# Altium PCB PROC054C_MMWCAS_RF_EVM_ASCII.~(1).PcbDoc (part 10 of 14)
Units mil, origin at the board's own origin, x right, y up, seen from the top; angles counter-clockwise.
Board outline 6299.21 x 5370.07 mil, 8 copper layers (L1 TOP, L2 GND, L3 SIGNAL 1, L4 GND, L5 SIGNAL 2, L6 SIGNAL 3, L7 GND, L8 BOTTOM), stack 53.5 mil thick; 775 components, 552 nets, 2648 pads, 7845 vias.
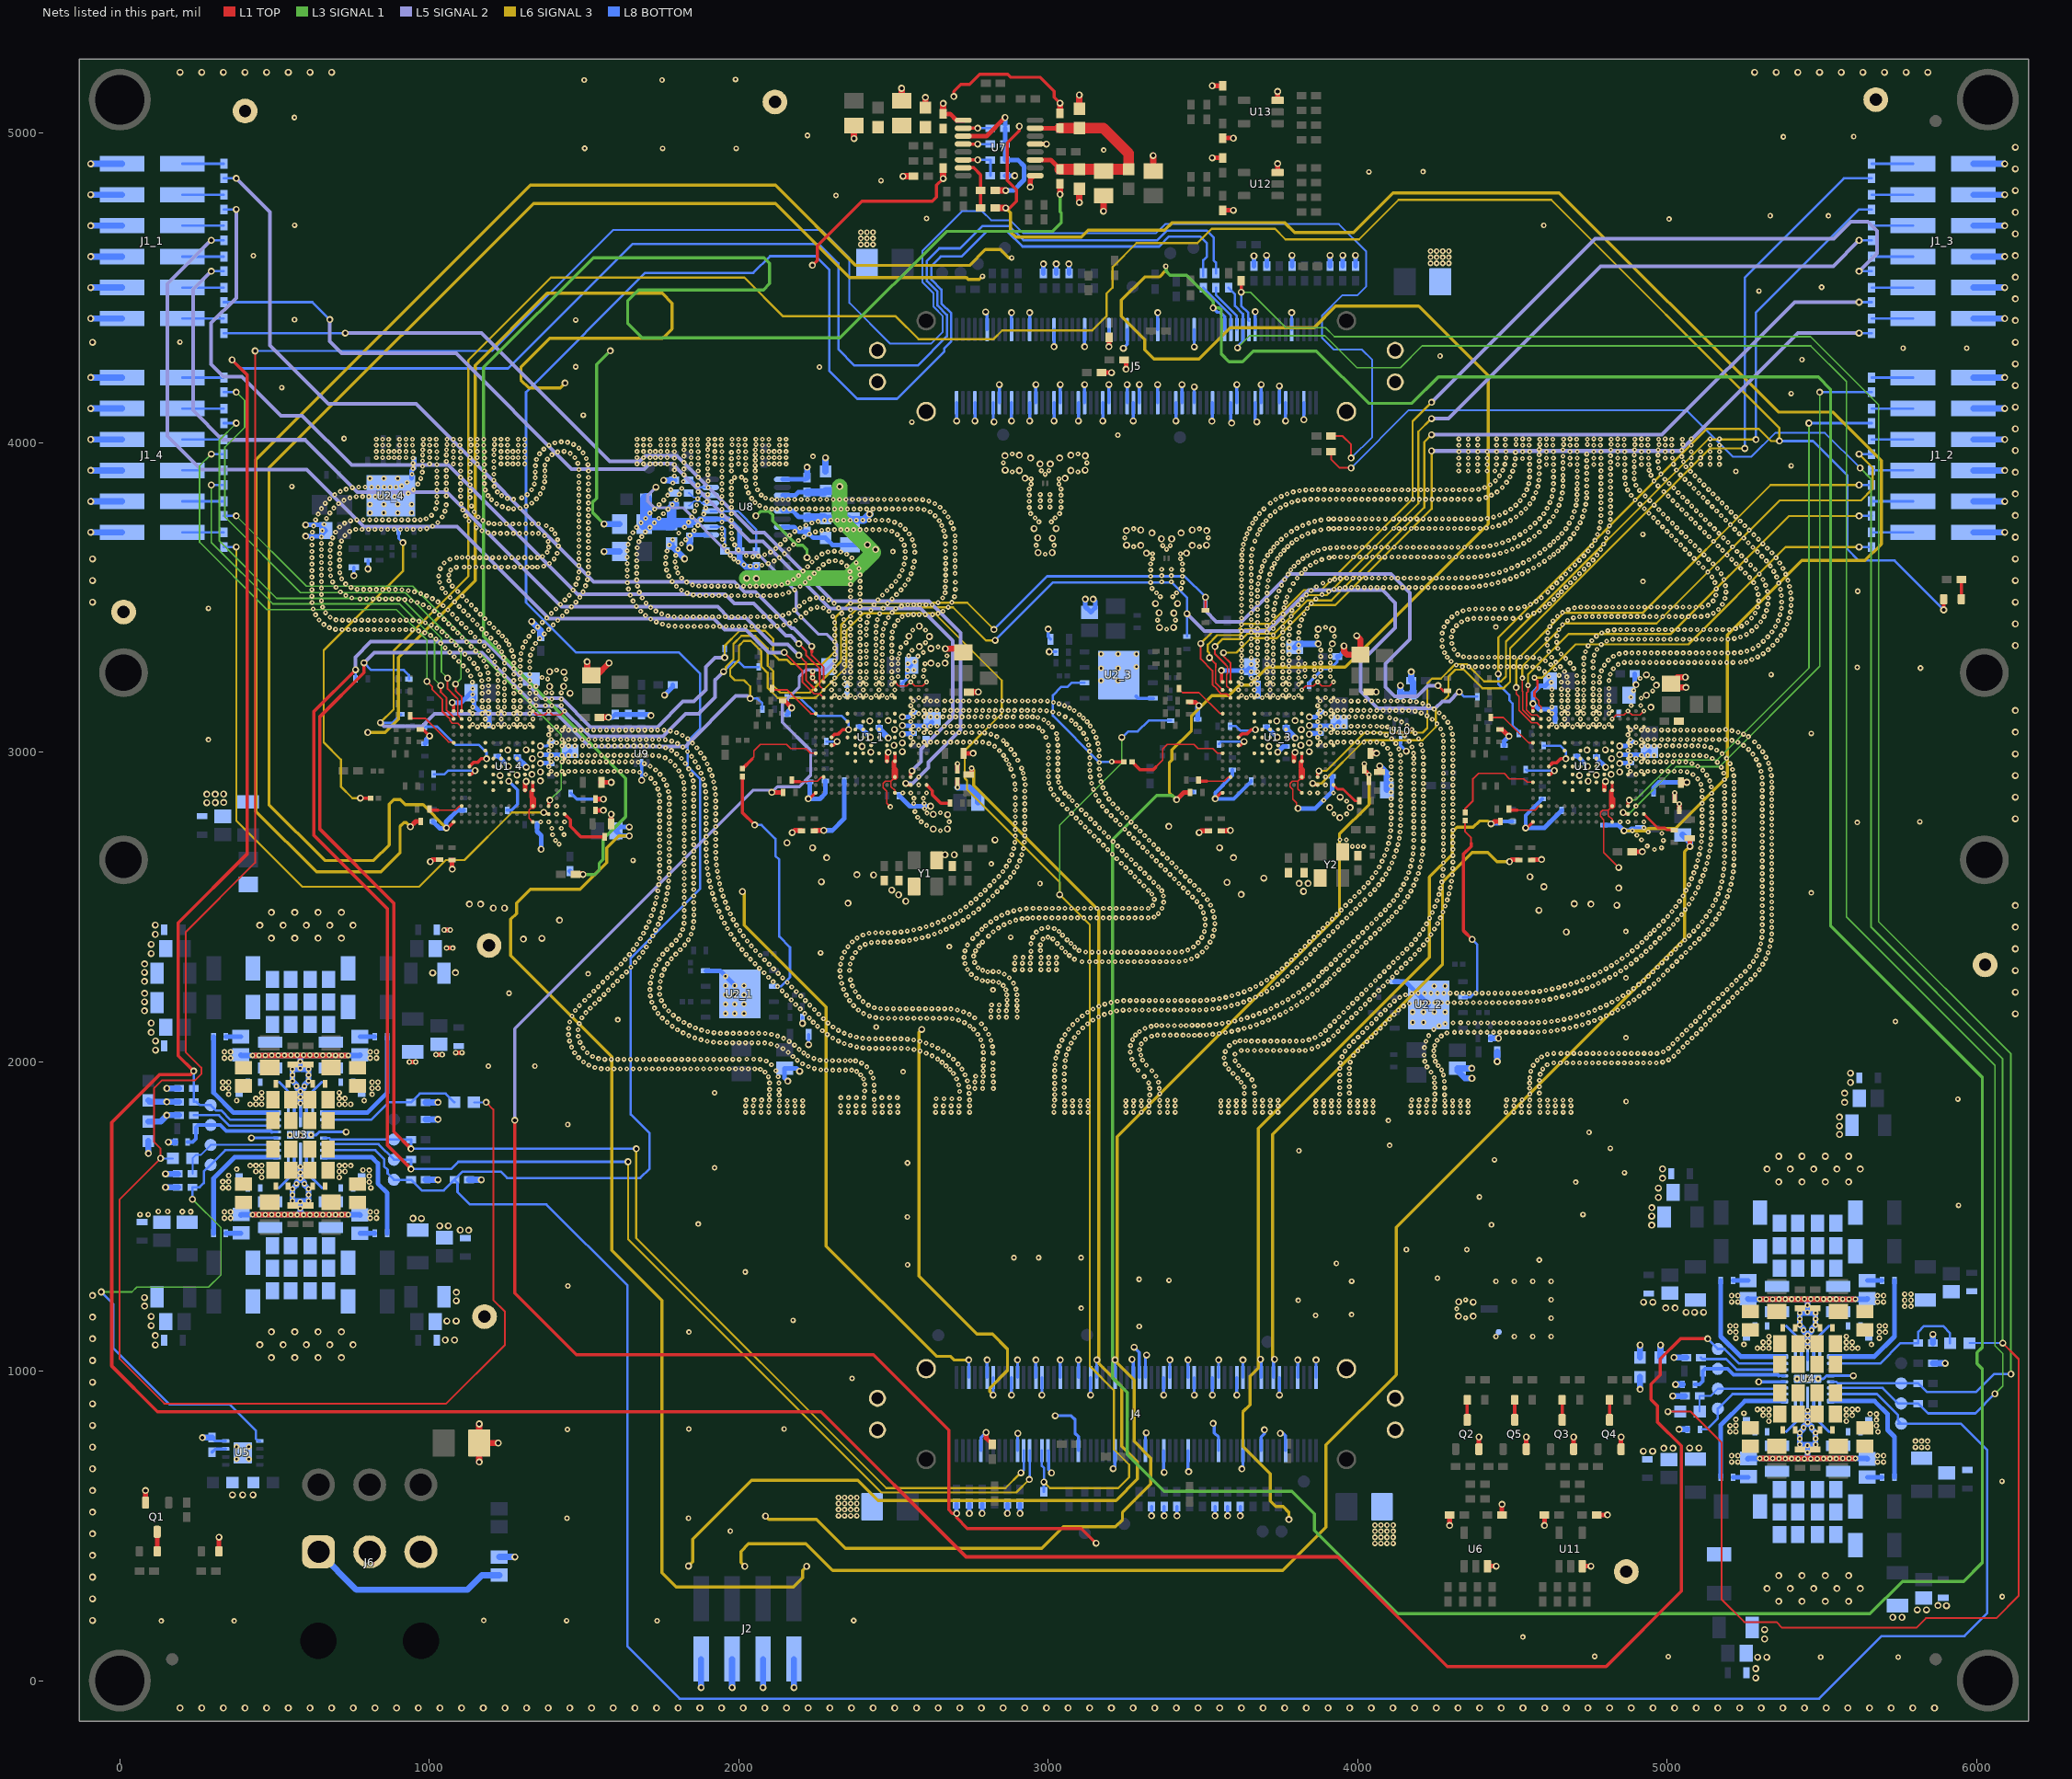
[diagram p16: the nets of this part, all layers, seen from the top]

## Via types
v1: diameter 13.77/15.74 (per signal layer), hole 5.9, L1 TOP to L2 GND, tented both sides, 5522 vias
v2: diameter 22.4, hole 12.2, L1 TOP to L8 BOTTOM, tented both sides, 1522 vias
v3: diameter 18, hole 8, L1 TOP to L8 BOTTOM, tented both sides, 727 vias
v4: diameter 18, hole 7.87, L1 TOP to L8 BOTTOM, tented top, 50 vias
v5: diameter 24, hole 12, L1 TOP to L8 BOTTOM, tented both sides, 13 vias
v6: diameter 19.68, hole 7.87, L1 TOP to L8 BOTTOM, tented top, 10 vias
v7: diameter 13.77/15.74 (per signal layer), hole 5.9, L1 TOP to L2 GND, tented top, 1 vias

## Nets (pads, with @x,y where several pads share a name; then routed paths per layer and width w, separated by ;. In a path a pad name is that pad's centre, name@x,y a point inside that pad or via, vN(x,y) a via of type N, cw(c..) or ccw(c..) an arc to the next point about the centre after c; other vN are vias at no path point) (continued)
GND: (continued)
  other v3: 5496.46,76.13 5746.88,75.69 5004.11,77.33 4766.22,78.16 4533.71,140.81 133.61,192.77 369.65,192.66 1735.9,193.46 1176.04,194.2 1443.98,193.71 2371.49,194.12 6083.21,271.3 4055.69,443.27 4075.37,443.27 4095.06,443.27 4114.74,443.27 4055.69,462.95 4075.37,462.95 4095.06,462.95 4114.74,462.95 1972.91,483.05 4055.69,482.64 4075.37,482.64 4095.06,482.64 4114.74,482.64 4055.69,502.32 4075.37,502.32 4095.06,502.32 4114.74,502.32 1444.93,524.87 1837.72,524.87 2322.39,532.65 2342.07,532.65 2361.76,532.65 2381.44,532.65 2322.39,552.33 2342.07,552.33 2361.76,552.33 2381.44,552.33 2322.39,572.02 2342.07,572.02 2361.76,572.02 2381.44,572.02 2322.39,591.7 2342.07,591.7 2361.76,591.7 2381.44,591.7 6082.36,644.09 5208.56,706.48 5228.64,706.48 5679.89,706.48 5699.97,706.48 5361.62,717.42 5382.2,717.42 5402.79,717.42 5423.38,717.03 5464.56,717.03 5485.14,717.03 5505.73,717.42 5526.32,717.42 5546.91,717.42 5208.56,726.56 5228.64,726.56 5679.89,726.56 5699.97,726.56 5453.83,737.78 5802.58,754.01 5822.27,754.01 5841.95,754.01 5480.24,762.36 5802.58,773.7 5822.27,773.7 5841.95,773.7 5480.24,781.54 5480.24,800.72 5203.41,804.46 5222.39,804.46 5681.81,804.28 1446.14,811.62 1838.91,813.25 2146.93,813.25 5467.25,817.49 5676.81,823.3 5203.39,824 5222.41,824.12 5676.81,842.33 5222.43,843.79 5676.81,861.35 5656.4,861.51 5248.32,864.12 2366.02,976.27 5248.32,1086.09 5660.21,1086.09 5222.43,1106.42 5686.1,1106.42 1839.11,1126.23 5203.39,1126.21 5222.41,1126.09 5686.12,1126.09 5705.13,1126.21 5467.25,1132.73 3294.2,1144.09 5203.41,1145.76 5222.39,1145.76 5686.14,1145.76 5705.12,1145.76 5480.24,1149.49 2175.59,1164.19 5480.24,1168.67 3863.89,1180.15 3980.44,1182.69 5480.24,1187.85 3106.88,1203.28 5768.24,1209.3 5787.93,1209.3 5453.83,1212.43 5208.56,1223.65 5228.64,1223.65 5679.89,1223.65 5699.97,1223.65 3808.19,1228.67 5768.24,1228.98 5787.93,1228.98 5361.62,1232.79 5382.2,1232.79 5402.79,1232.79 5423.38,1233.18 5464.56,1233.18 5485.14,1233.18 5505.73,1232.79 5526.32,1232.79 5546.91,1232.79 5208.56,1243.73 5228.64,1243.73 5679.89,1243.73 5699.97,1243.73 5768.24,1248.67 5787.93,1248.67 1447.63,1274.99 3980.74,1290.5 3390.59,1293.49 3294.08,1296.71 4258.14,1300.39 2020.86,1320.43 2545.46,1343.65 3931.42,1348.07 4587.06,1359.02 2889.33,1366.57 2969.15,1366.57 3106.43,1366.57 4353.05,1392.49 4157.58,1392.65 4432.48,1472.84 1869.17,1475.16 337.84,1494.34 357.91,1494.34 809.16,1494.34 829.24,1494.34 2544.96,1497.98 490.89,1505.28 511.48,1505.28 532.07,1505.28 552.66,1504.88 593.83,1504.88 614.42,1504.88 635.01,1505.28 655.6,1505.28 676.18,1505.28 65.22,1505.76 91.7,1505.76 4728.35,1506.03 337.84,1514.42 357.91,1514.42 809.16,1514.42 829.24,1514.42 201.83,1515.15 228.74,1515.15 124.35,1515.58 154.44,1515.58 583.11,1525.63 5942.02,1535.47 609.51,1550.22 4393.83,1562.75 609.51,1569.4 609.51,1588.57 332.68,1592.31 351.66,1592.31 811.08,1592.13 596.53,1605.34 806.08,1611.16 4704.66,1610.58 332.67,1611.86 351.68,1611.98 806.08,1630.18 351.7,1631.65 4862.1,1641.27 785.68,1649.37 806.08,1649.21 377.59,1651.98 1922,1656.9 2545.38,1672.67 4442.29,1682.92 3810.04,1712.1 4816.83,1720.08 4103.53,1729.5 4748.01,1771.34 1447.49,1796.86 4099.3,1809.49 4867.67,1870.96 377.59,1873.94 789.48,1873.94 5939.7,1878.97 351.7,1894.28 815.37,1894.28 1922,1899.1 332.67,1914.07 351.68,1913.94 815.39,1913.94 834.41,1914.07 596.53,1920.58 332.68,1933.61 351.66,1933.61 815.41,1933.61 834.39,1933.61 609.51,1937.35 609.51,1956.53 2531.24,1967.09 609.51,1975.71 1190.66,1985.23 1341.2,1985.23 583.11,2000.29 337.84,2011.51 357.91,2011.51 809.16,2011.51 829.24,2011.51 490.89,2020.65 511.48,2020.65 532.07,2020.65 552.66,2021.04 593.83,2021.04 614.42,2021.04 635.01,2020.65 655.6,2020.65 676.18,2020.65 337.84,2031.58 357.91,2031.58 809.16,2031.58 829.24,2031.58 4867.09,2077.1 2444.27,2111.49 5737.78,2129.64 1609.07,2135.05 1257.6,2220.99 2821.69,2231.51 4866.97,2270.39 1513.34,2283.69 2264.44,2351.62 2680.48,2371.52 2878.65,2401.99 4866.57,2420.19 5466.22,2545.1 2973.41,2575.67 2815.94,2638.69 1658.33,2650.13 5614.76,2772.56 5816.69,2774.88 286.24,3040.08 5466.22,3060.36 5336.44,3250.52 5819.01,3271.58 5614.76,3273.9 4446.74,3404.24 286.24,3464.59 5616.14,3519.73 4922.12,3551.17 2498.15,3647.68 4921.9,3703.62 555.74,3858.48 5222.3,3906.93 5401.14,3925.27 2239.73,3955.33 724.55,4013.2 3225.12,4024.15 2559.67,4066.48 1497.64,4088.75 5401.14,4158.65 523.21,4177.95 2260.51,4244.03 1473.37,4244.89 5435.94,4267.85 4266.52,4279.69 5762.98,4305.17 5968.42,4305.17 194.01,4324.78 1473.37,4396.3 564.38,4397.12 5297.15,4489.7 5499.56,4501.97 4235.61,4579.25 4255.29,4579.25 4274.98,4579.25 4294.66,4579.25 4235.61,4598.94 4255.29,4598.94 4274.98,4598.94 4294.66,4598.94 431.7,4603.8 4235.61,4618.62 4255.29,4618.62 4274.98,4618.62 4294.66,4618.62 2394.49,4640.14 2414.18,4640.14 2433.86,4640.14 2394.49,4659.82 2414.18,4659.82 2433.86,4659.82 2394.49,4679.51 2414.18,4679.51 2433.86,4679.51 564.74,4702.39 4601.73,4701.99 5006.36,4722.28 2607.24,4724.16 5333.41,4733.02 5521.43,4732.67 2314.4,4798.51 2459.82,4846.58 4036.41,4874.63 4211.46,4875.14 3179.55,4945.14 1502.16,4950.81 1753.92,4950.6 1991.93,4950.6 5375.87,4987.98 5603.32,4988.7 2221.82,4992.4 564.12,5050.42 1500.65,5171.71 1752.01,5171.71 1989.61,5173.43
  other v4: 4447.2,1111.73 4506.58,1111.73 4565.95,1111.73 4625.33,1111.73 4625.33,1171.11 4625.33,1230.48 4447.2,1289.85 4506.58,1289.85 4565.95,1289.85 4625.33,1289.85 4177.99,2126.74 4213.08,2126.74 1957.07,2155.57 1987.07,2155.57 2017.07,2155.57 4177.6,2160.03 4212.7,2160.03 4247.79,2160.03 4282.88,2160.03 1957.07,2185.57 1987.07,2185.57 2017.07,2185.57 1957.07,2215.57 1987.07,2215.57 2017.07,2215.57 4247.51,2243.88 4282.61,2243.88 1957.07,2245.57 1987.07,2245.57 2017.07,2245.57 1957.07,2275.57 3170.96,3230.95 3225.96,3230.95 3170.96,3270.95 3225.96,3270.95 3284.96,3275.95 3170.96,3316.95 3225.96,3316.95 3284.96,3316.95 808.11,3773.1 853.11,3773.1 898.11,3773.1 943.11,3773.1 808.11,3800.1 853.11,3800.1 898.11,3800.1 943.11,3800.1 808.11,3884.1 853.11,3884.1 898.11,3884.1
  other v6: 377.44,716.09 416.81,716.09 377.44,755.46 416.81,755.46 5420.01,975.11 549.29,1762.96
  other v7: 1435.24,2733.62
GND_SENSE: J6.1 R20.2 | length 654.6
  L8 BOTTOM w20: J6.1@642.01,416.24 764.9,293.36 1122.57,293.36 1169.82,340.61 R20.2@1226.16,340.61
GPADC1_1: R21_1.1 U1_1.P1 | length 2910.5
  L1 TOP w6: 2235.94,3323.61 2235.94,3313.08 2274.35,3274.67 U1_1.P1@2274.35,3226.63
  L1 TOP w10.5: 2235.94,3323.61 v2(2235.94,3341.84)
  L5 SIGNAL 2 w12: v2(376.34,4853.71) 484.59,4745.46 484.59,4313.48 673.16,4124.91 957.25,4124.91 1531.42,3550.74 1985.84,3550.74 2019.19,3517.39 2054.28,3517.39 2171.25,3400.42 2177.35,3400.42 v2(2235.94,3341.84)
  L8 BOTTOM w7.75: R21_1.1@335.85,4853.71 v2(376.34,4853.71)
GPADC1_2: R21_2.1 U1_2.P1 | length 1388.9
  L1 TOP w4: 4571.43,3180.57 4586.04,3165.96 4586.04,3152.41 4592.35,3146.1 U1_2.P1@4592.35,3132.63
  L1 TOP w8: 4571.43,3180.57 4571.43,3195.32 4580.76,3204.64 4580.76,3231.14 v3(4571.43,3240.47)
  L6 SIGNAL 3 w6.9: v3(4571.43,3240.47) 4596.67,3240.47 4704.44,3348.24 5069.13,3348.24 5383.78,3662.89 v2(5620.66,3662.89)
  L8 BOTTOM w7.75: v2(5620.66,3662.89) R21_2.1@5661.15,3662.89
GPADC1_3: R21_3.1 U1_3.P1 | length 2735.9
  L1 TOP w6: v2(3566.57,3321.12) 3566.57,3310 3589.35,3287.22 U1_3.P1@3589.35,3226.63
  L5 SIGNAL 2 w12: v2(4239,3973) 5042.9,3973 5423.61,4353.71 v2(5620.66,4353.71)
  L6 SIGNAL 3 w6.9: v2(3566.57,3321.12) 3608.23,3321.12 3655.5,3368.4 3739.36,3368.4 3845.99,3475.03 3928.21,3475.03 4239,3785.82 v2(4239,3973)
  L8 BOTTOM w7.75: v2(5620.66,4353.71) R21_3.1@5661.15,4353.71
GPADC1_4: R21_4.1 U1_4.P1 | length 1637.4
  L1 TOP w6: v2(1085,3220) 1085,3199.39 1104.35,3180.04 U1_4.P1@1104.35,3132.63
  L3 SIGNAL 1 w5.1: v2(376.34,4162.89) 403.51,4135.72 403.51,4049.61 339.61,3985.71 339.61,3759.61 584.15,3515.07 922.18,3515.07 1102.11,3335.14 1102.11,3237.11 v2(1085,3220)
  L8 BOTTOM w7.75: R21_4.1@335.85,4162.89 v2(376.34,4162.89)
GPADC1_CONN_1: J1_1.1 R21_1.2 | length 133.6
  L8 BOTTOM w7.75: J1_1.1@202.2,4900.95 R21_1.2@335.85,4900.95
GPADC1_CONN_2: J1_2.1 R21_2.2 | length 133.6
  L8 BOTTOM w7.75: R21_2.2@5661.15,3710.13 J1_2.1@5794.8,3710.13
GPADC1_CONN_3: J1_3.1 R21_3.2 | length 133.6
  L8 BOTTOM w7.75: R21_3.2@5661.15,4400.95 J1_3.1@5794.8,4400.95
GPADC1_CONN_4: J1_4.1 R21_4.2 | length 133.6
  L8 BOTTOM w7.75: J1_4.1@202.2,4210.13 R21_4.2@335.85,4210.13
GPADC2_1: R22_1.1 U1_1.P2 | length 3029.7
  L1 TOP w4: 2261.49,3235.84 2261.49,3213.9 U1_1.P2@2274.35,3201.04
  L1 TOP w6: v2(2194.09,3349.92) 2217.73,3326.28 2217.73,3313.24 2261.49,3269.48 2261.49,3235.84
  L5 SIGNAL 2 w12: v2(376.34,4753.71) 376.34,4467.74 295.19,4386.59 295.19,4253.33 335.16,4213.35 394.52,4213.35 520.64,4087.23 588.93,4087.23 748.84,3927.31 1061.01,3927.31 1478.43,3509.89 1955.91,3509.89 1985.77,3480.03 2048.08,3480.03 2152.21,3375.91 2168.1,3375.91 v2(2194.09,3349.92)
  L8 BOTTOM w7.75: R22_1.1@335.85,4753.71 v2(376.34,4753.71)
GPADC2_2: R22_2.1 U1_2.P2 | length 1497.9
  L1 TOP w4: 4545.62,3148.38 4545.62,3136.09 4561.81,3119.9 4579.49,3119.9 U1_2.P2@4592.35,3107.04
  L1 TOP w6: 4545.62,3148.38 4545.62,3191.12 4550.87,3196.38 v3(4550.87,3216.09)
  L6 SIGNAL 3 w6.9: v3(4550.87,3216.09) 4550.87,3250.62 4682.25,3381.99 5012.95,3381.99 5393.85,3762.89 v2(5620.66,3762.89)
  L8 BOTTOM w7.75: v2(5620.66,3762.89) R22_2.1@5661.15,3762.89
GPADC2_3: R22_3.1 U1_3.P2 | length 2870
  L1 TOP w4: 3573.3,3282.68 3579.29,3276.69 3579.29,3253.3 3576.39,3250.39 3576.39,3214 U1_3.P2@3589.35,3201.04
  L1 TOP w6: v2(3539,3341) 3539,3316.99 3573.3,3282.68
  L5 SIGNAL 2 w12: v2(4239,4025.33) 4983.76,4025.33 5412.13,4453.71 v2(5620.66,4453.71)
  L6 SIGNAL 3 w6.9: v2(3539,3341) 3562.87,3364.87 3625.69,3364.87 3643.85,3383.03 3730.83,3383.03 3838.22,3490.42 3915.31,3490.42 4215.47,3790.59 4215.47,4001.81 v2(4239,4025.33)
  L8 BOTTOM w7.75: v2(5620.66,4453.71) R22_3.1@5661.15,4453.71
GPADC2_4: R22_4.1 U1_4.P2 | length 1579.6
  L1 TOP w4: 1086.33,3177.31 1091.49,3172.15 1091.49,3119.9 U1_4.P2@1104.35,3107.04
  L1 TOP w6: v2(1059,3239) 1059,3204.64 1086.33,3177.31
  L3 SIGNAL 1 w5.1: v2(376.34,4062.89) 321.76,4008.31 321.76,3681.81 507.14,3496.43 910.93,3496.43 1039.1,3368.26 1039.1,3258.9 v2(1059,3239)
  L8 BOTTOM w7.75: R22_4.1@335.85,4062.89 v2(376.34,4062.89)
GPADC2_CONN_1: J1_1.3 R22_1.2 | length 133.6
  L8 BOTTOM w7.75: J1_1.3@202.2,4800.95 R22_1.2@335.85,4800.95
GPADC2_CONN_2: J1_2.3 R22_2.2 | length 133.6
  L8 BOTTOM w7.75: R22_2.2@5661.15,3810.13 J1_2.3@5794.8,3810.13
GPADC2_CONN_3: J1_3.3 R22_3.2 | length 133.6
  L8 BOTTOM w7.75: R22_3.2@5661.15,4500.95 J1_3.3@5794.8,4500.95
GPADC2_CONN_4: J1_4.3 R22_4.2 | length 133.6
  L8 BOTTOM w7.75: J1_4.3@202.2,4110.13 R22_4.2@335.85,4110.13
GPADC3_1: R23_1.1 U1_1.P3 | length 3224.7
  L1 TOP w4: 2232,3200 2244,3188 2261.8,3188 U1_1.P3@2274.35,3175.45
  L1 TOP w6: v2(2147,3322) 2205.54,3263.46 2205.54,3226.46 2232,3200
  L5 SIGNAL 2 w12: v2(295.35,4653.71) 294.32,4653.71 154.03,4513.42 154.03,4020.74 262.2,3912.57 604.09,3912.57 787.75,3728.91 1089.55,3728.91 1387.22,3431.24 1919.62,3431.24 1954.92,3395.94 2022.73,3395.94 2096.68,3322 v2(2147,3322)
  L8 BOTTOM w7.75: v2(295.35,4653.71) R23_1.1@335.85,4653.71
GPADC3_2: R23_2.1 U1_2.P3 | length 1641.4
  L1 TOP w4: v2(4512.4,3208.76) 4512.4,3187.71 4521,3179.11 4521,3135.12 4561.72,3094.4 4579.4,3094.4 U1_2.P3@4592.35,3081.45
  L6 SIGNAL 3 w6.9: v2(4512.4,3208.76) 4512.4,3295.65 4666.98,3450.24 4922.03,3450.24 5334.68,3862.89 v2(5620.66,3862.89)
  L8 BOTTOM w7.75: v2(5620.66,3862.89) R23_2.1@5661.15,3862.89
GPADC3_3: R23_3.1 U1_3.P3 | length 3330.3
  L1 TOP w4: 3545.01,3204.7 3549.01,3200.7 3549.01,3198.11 3559.12,3188 3576.8,3188 U1_3.P3@3589.35,3175.45
  L1 TOP w6: v2(3493,3351) 3493,3300.94 3531,3262.94 3531,3218.71 3545.01,3204.7
  L5 SIGNAL 2 w12: v2(4239,4130) 4768.28,4659.28 5538.33,4659.28 5593.44,4714.39 5648.8,4714.39 5678.49,4684.7 5678.49,4611.54 v2(5620.66,4553.71)
  L6 SIGNAL 3 w6.9: v2(3493,3351) 3532.52,3390.52 3609.42,3390.52 3632.96,3414.05 3716.75,3414.05 3826.38,3523.68 3882.78,3523.68 4177.51,3818.41 4177.51,4068.51 v2(4239,4130)
  L8 BOTTOM w7.75: v2(5620.66,4553.71) R23_3.1@5661.15,4553.71
GPADC3_4: R23_4.1 U1_4.P3 | length 1543.5
  L1 TOP w4: 1060.89,3113.01 1066,3107.91 1066,3102.12 1074.12,3094 1091.8,3094 U1_4.P3@1104.35,3081.45
  L1 TOP w6: v2(992.5,3228.5) 1009.75,3211.25 1009.75,3202.06 1042.64,3169.17 1042.64,3131.27 1060.89,3113.01
  L3 SIGNAL 1 w5.1: v2(295.35,3962.89) 257.78,3925.32 257.78,3678.26 475.52,3460.52 893.72,3460.52 992.5,3361.74 v2(992.5,3228.5)
  L8 BOTTOM w7.75: v2(295.35,3962.89) R23_4.1@335.85,3962.89
GPADC3_CONN_1: J1_1.5 R23_1.2 | length 133.6
  L8 BOTTOM w7.75: J1_1.5@202.2,4700.95 R23_1.2@335.85,4700.95
GPADC3_CONN_2: J1_2.5 R23_2.2 | length 133.6
  L8 BOTTOM w7.75: R23_2.2@5661.15,3910.13 J1_2.5@5794.8,3910.13
GPADC3_CONN_3: J1_3.5 R23_3.2 | length 133.6
  L8 BOTTOM w7.75: R23_3.2@5661.15,4600.95 J1_3.5@5794.8,4600.95
GPADC3_CONN_4: J1_4.5 R23_4.2 | length 133.6
  L8 BOTTOM w7.75: J1_4.5@202.2,4010.13 R23_4.2@335.85,4010.13
GPADC4_1: R24_1.1 U1_1.R2 | length 2934.6
  L1 TOP w6: v2(2194,3313) 2217.36,3289.64 2217.36,3232.44 U1_1.R2@2248.76,3201.04
  L5 SIGNAL 2 w12: v2(295.35,4553.71) 236.32,4494.67 236.32,4103.95 331.66,4008.61 599.55,4008.61 767.72,3840.44 1057,3840.44 1427.48,3469.96 1931.72,3469.96 1968.47,3433.21 2025.07,3433.21 2109.53,3348.75 2158.25,3348.75 v2(2194,3313)
  L8 BOTTOM w7.75: v2(295.35,4553.71) R24_1.1@335.85,4553.71
GPADC4_2: R24_2.1 U1_2.R2 | length 1726.8
  L1 TOP w4: v3(4532.25,3239.26) 4532.25,3197.82 4534,3196.07 4534,3136.39 4563.35,3107.04 U1_2.R2@4566.76,3107.04
  L6 SIGNAL 3 w6.9: v3(4532.25,3239.26) 4532.25,3277.3 4670.69,3415.74 4966.32,3415.74 5364,3813.42 5627.23,3813.42 5664.09,3850.28 5664.09,3919.46 v2(5620.66,3962.89)
  L8 BOTTOM w7.75: v2(5620.66,3962.89) R24_2.1@5661.15,3962.89
GPADC4_3: R24_3.1 U1_3.R2 | length 2987.8
  L1 TOP w4: 3541,3274.11 3541,3223.8 U1_3.R2@3563.76,3201.04
  L1 TOP w6: v2(3521,3305) 3541,3285 3541,3274.11
  L5 SIGNAL 2 w12: v2(4239,4077.67) 4293.28,4077.67 4785.87,4570.26 5537.22,4570.26 v2(5620.66,4653.71)
  L6 SIGNAL 3 w6.9: v2(3521,3305) 3521,3320.12 3516.15,3324.97 3516.15,3347.27 3546.53,3377.64 3617.31,3377.64 3636.67,3397 3722.08,3397 3832.27,3507.19 3900.24,3507.19 4196.51,3803.45 4196.51,4035.18 v2(4239,4077.67)
  L8 BOTTOM w7.75: v2(5620.66,4653.71) R24_3.1@5661.15,4653.71
GPADC4_4: R24_4.1 U1_4.R2 | length 1360.4
  L1 TOP w4: 1065.38,3126.62 1078.76,3113.24 U1_4.R2@1078.76,3107.04
  L1 TOP w6: v2(1037,3215) 1037,3194.33 1055.19,3176.15 1055.19,3136.81 1065.38,3126.62
  L3 SIGNAL 1 w5.1: v2(295.35,3862.89) 295.35,3677.72 493.91,3479.17 902.79,3479.17 1017.02,3364.94 1017.02,3234.98 v2(1037,3215)
  L8 BOTTOM w7.75: v2(295.35,3862.89) R24_4.1@335.85,3862.89
GPADC4_CONN_1: J1_1.7 R24_1.2 | length 133.6
  L8 BOTTOM w7.75: J1_1.7@202.2,4600.95 R24_1.2@335.85,4600.95
GPADC4_CONN_2: J1_2.7 R24_2.2 | length 133.6
  L8 BOTTOM w7.75: R24_2.2@5661.15,4010.13 J1_2.7@5794.8,4010.13
GPADC4_CONN_3: J1_3.7 R24_3.2 | length 133.6
  L8 BOTTOM w7.75: R24_3.2@5661.15,4700.95 J1_3.7@5794.8,4700.95
GPADC4_CONN_4: J1_4.7 R24_4.2 | length 133.6
  L8 BOTTOM w7.75: J1_4.7@202.2,3910.13 R24_4.2@335.85,3910.13
GPADC5_1: R25_1.1 U1_1.C13 | length 3361.4
  L1 TOP w10.5: U1_1.C13@2555.84,2919.55 2555.84,2935.15 v2(2559.59,2938.9)
  L5 SIGNAL 2 w12: v2(678.21,4397.34) 678.21,4326.9 716.82,4288.29 1086.57,4288.29 1460.09,3914.77 1694.43,3914.77 1711.84,3932.18 1785.55,3932.18 2036.9,3680.83 2078.26,3680.83 2294.99,3464.11 2587.27,3464.11 2692.07,3359.31 2692.07,3111.65 2589.83,3009.4 2589.83,2969.14 v2(2559.59,2938.9)
  L8 BOTTOM w7.75: R25_1.1@335.85,4453.71 621.84,4453.71 v2(678.21,4397.34)
GPADC5_2: R25_2.1 U1_2.C13 | length 1772.4
  L1 TOP w10.5: U1_2.C13@4873.84,2825.55 4873.84,2840.9 4877.84,2844.9 v2(4878,2844.9)
  L3 SIGNAL 1 w5.1: v2(4878,2844.9) 4898.17,2844.9 5027.55,2974.28 5161.26,2974.28 5458.45,3271.47 v2(5458.45,4062.89)
  L8 BOTTOM w7.75: v2(5458.45,4062.89) R25_2.1@5661.15,4062.89
GPADC5_3: R25_3.1 U1_3.C13 | length 2996.4
  L1 TOP w10.5: U1_3.C13@3870.84,2919.55 3870.84,2935.15 v2(3875.07,2939.38)
  L6 SIGNAL 3 w6.9: v2(3875.07,2939.38) 3899.08,2939.38 4022.53,3062.83 4210.63,3062.83 4225.16,3077.37 4225.16,3221.8 4240.48,3237.11 4269.21,3237.11 4316.25,3284.15 4353.32,3284.15 4409.02,3228.45 4463.36,3228.45 4479.21,3244.3 4479.21,3356.97 5132.2,4009.96 v2(5287.35,4009.96)
  L8 BOTTOM w7.75: v2(5287.35,4009.96) 5287.35,4420.4 5620.66,4753.71 R25_3.1@5661.15,4753.71
GPADC5_4: R25_4.1 U1_4.C13 | length 1630.3
  L1 TOP w10.5: U1_4.C13@1385.84,2825.55 1385.84,2841.15 v2(1389.59,2844.9)
  L3 SIGNAL 1 w5.1: v2(376.34,3762.89) 603.44,3535.79 946.79,3535.79 1425.94,3056.63 1425.94,2881.25 v2(1389.59,2844.9)
  L8 BOTTOM w7.75: R25_4.1@335.85,3762.89 v2(376.34,3762.89)
GPADC5_CONN_1: J1_1.9 R25_1.2 | length 133.6
  L8 BOTTOM w7.75: J1_1.9@202.2,4500.95 R25_1.2@335.85,4500.95
GPADC5_CONN_2: J1_2.9 R25_2.2 | length 133.6
  L8 BOTTOM w7.75: R25_2.2@5661.15,4110.13 J1_2.9@5794.8,4110.13
GPADC5_CONN_3: J1_3.9 R25_3.2 | length 133.6
  L8 BOTTOM w7.75: R25_3.2@5661.15,4800.95 J1_3.9@5794.8,4800.95
GPADC5_CONN_4: J1_4.9 R25_4.2 | length 133.6
  L8 BOTTOM w7.75: J1_4.9@202.2,3810.13 R25_4.2@335.85,3810.13
GPADC6_1: R26_1.1 U1_1.C14 | length 3387.5
  L1 TOP w10.5: v2(2540,2899) 2545.04,2893.96 U1_1.C14@2555.85,2893.95
  L5 SIGNAL 2 w12: v2(728.54,4353.71) 1168.43,4353.71 1583.26,3938.87 1680.07,3938.87 1698.74,3957.54 1799.67,3957.54 2048.49,3708.72 2083.01,3708.72 2304.42,3487.3 2614.38,3487.3 2716.85,3384.84 2716.85,3071.47 2612.98,2967.61 2612.98,2950.24 2561.74,2899 v2(2540,2899)
  L8 BOTTOM w7.75: R26_1.1@335.85,4353.71 v2(728.54,4353.71)
GPADC6_2: R26_2.1 U1_2.C14 | length 1902.4
  L1 TOP w10.5: v2(4858,2805) 4863.04,2799.96 U1_2.C14@4873.85,2799.95
  L3 SIGNAL 1 w5.1: v2(4858,2805) 4881.3,2805 5029.27,2952.97 5169.09,2952.97 5493.28,3277.16 v2(5493.28,4162.89)
  L8 BOTTOM w7.75: v2(5493.28,4162.89) R26_2.1@5661.15,4162.89
GPADC6_3: R26_3.1 U1_3.C14 | length 3142.1
  L1 TOP w10.5: v2(3855,2899) 3860.04,2893.96 U1_3.C14@3870.85,2893.95
  L6 SIGNAL 3 w6.9: v2(3855,2899) 3883.22,2899 4022.41,3038.18 4209.96,3038.18 4252.96,3081.18 4252.96,3141.71 4293.66,3182.41 4293.66,3244.39 4315.65,3266.37 4343.21,3266.37 4402.97,3206.6 4472.25,3206.6 4492.94,3227.29 4492.94,3335.73 5138.35,3981.15 v2(5251.44,3981.15)
  L8 BOTTOM w7.75: v2(5251.44,3981.15) 5251.44,4533.41 5571.73,4853.71 R26_3.1@5661.15,4853.71
GPADC6_4: R26_4.1 U1_4.C14 | length 2124.3
  L1 TOP w10.5: v2(1370,2805) 1377.56,2805 1382.6,2799.96 U1_4.C14@1385.85,2799.95
  L6 SIGNAL 3 w6.9: v2(376.34,3662.89) 376.34,2778.36 589.61,2565.09 967.45,2565.09 1053.48,2651.12 1113.4,2651.12 1267.28,2805 v2(1370,2805)
  L8 BOTTOM w7.75: R26_4.1@335.85,3662.89 v2(376.34,3662.89)
GPADC6_CONN_1: J1_1.11 R26_1.2 | length 133.6
  L8 BOTTOM w7.75: J1_1.11@202.2,4400.95 R26_1.2@335.85,4400.95
GPADC6_CONN_2: J1_2.11 R26_2.2 | length 133.6
  L8 BOTTOM w7.75: R26_2.2@5661.15,4210.13 J1_2.11@5794.8,4210.13
GPADC6_CONN_3: J1_3.11 R26_3.2 | length 133.6
  L8 BOTTOM w7.75: R26_3.2@5661.15,4900.95 J1_3.11@5794.8,4900.95
GPADC6_CONN_4: J1_4.11 R26_4.2 | length 133.6
  L8 BOTTOM w7.75: J1_4.11@202.2,3710.13 R26_4.2@335.85,3710.13
LMK1_1V8: C176.1 C177.1 C178.2 C179.1 C180.2 L34.2 U7.11 U7.15 | length 706.4
  L1 TOP w15: U7.11@2957.85,4913.54 3007.99,4913.54 C177.1@3038.3,4883.23 ; U7.15@2957.85,5015.9 C179.1@3038.3,5015.9
  L1 TOP w35: C177.1@3038.3,4883.23 C180.2@3100.57,4883.23 3173.37,4883.23 C176.1@3178.88,4877.72 3184.4,4883.23 L34.2@3260.01,4883.23 3260.01,4934.5 3178.6,5015.9 C178.2@3100.57,5015.9 C179.1@3038.3,5015.9
LMK1_3V3: C170.1 C171.2 C172.1 L33.2 R105.2 R118.2 R119.2 R120.2 U7.3 | length 508.9
  L1 TOP w15: U7.3@2725.57,4990.31 2800.52,4990.31 v2(2860.62,5050.41)
  L1 TOP w20: R118.2@2829.26,4814.5 v2(2862.9,4814.5)
  L8 BOTTOM w15: R120.2@2860.62,5015.9 R119.2@2860.62,4964.72 R105.2@2860.62,4913.54 2901.99,4913.54 2922.25,4893.28 2922.25,4849.05 2887.69,4814.5 v2(2862.9,4814.5) ; R120.2@2860.62,5025.41 v2(2860.62,5050.41)
LMK1_CLK_EN: R119.1 U7.4 | length 87.8
  L1 TOP w10.5: U7.4@2725.57,4964.72 v2(2772.02,4964.72)
  L8 BOTTOM w7.75: v2(2772.02,4964.72) R119.1@2813.38,4964.72
LMK1_CLK_SEL: R118.1 R124.2 U7.7 | length 173
  L1 TOP w10.5: U7.7@2725.57,4887.95 2759.21,4887.95 2782.02,4865.14 R124.2@2782.02,4758.04
LMK1_nCLK: R105.1 R110.2 U7.6 | length 139
  L1 TOP w10.5: U7.6@2725.57,4913.54 v2(2772.02,4913.54)
  L8 BOTTOM w7.75: v2(2772.02,4913.54) R105.1@2813.38,4913.54 R110.2@2813.38,4862.36
LMK1_OE: R120.1 U7.2 | length 87.8
  L1 TOP w10.5: U7.2@2725.57,5015.9 v2(2772.02,5015.9)
  L8 BOTTOM w7.75: v2(2772.02,5015.9) R120.1@2813.38,5015.9
LMK2_3V3: C182.1 C183.2 C184.1 C185.1 C186.1 C187.2 C188.1 C189.2 L35.2 R137.2 R138.2 R141.2 U8.3 U8.11 U8.15 | length 1865.2
  L3 SIGNAL 1 w50: v2(2025.66,3561.87) 2351.99,3561.87 2435.46,3645.34 2326.38,3754.41 v2(2326.38,3858.27)
  L8 BOTTOM w15: C182.1@1841.77,3741.12 1860.89,3741.12 1872.78,3753 U8.3@1908.9,3753 1968.09,3753 2002.94,3718.16 R138.2@2002.94,3649.64 ; U8.15@2141.18,3727.41 2179.18,3727.41 2194.37,3712.23 C186.1@2220.98,3712.23 2240.83,3692.37 C187.2@2280.22,3692.37 2302.89,3669.7 C185.1@2359.46,3669.7 v2(2416.03,3669.7) ; U8.11@2141.18,3829.78 2182.94,3829.78 2192.59,3839.43 C188.1@2220.98,3839.43
  L8 BOTTOM w20: R138.2@2002.94,3649.64 2002.94,3618.65 2023.14,3598.46 R137.2@2056.85,3598.46 v2(2056.85,3561.16)
  L8 BOTTOM w25: C188.1@2220.98,3839.43 2276.12,3839.43 C189.2@2280.22,3843.53 2311.65,3843.53 v2(2326.38,3858.27)
  L8 BOTTOM w30: C184.1@1695.02,3737.01 C184.1@1700.53,3742.52 ; R141.2@1791.14,3796.29 1783.09,3788.23 1783.09,3741.12 C182.1@1841.77,3741.12
  L8 BOTTOM w40: C184.1@1695.02,3737.01 C183.2@1783.09,3737.01 ; C184.1@1700.53,3742.52 L35.2@1700.53,3816.87
  other v2: 2442.4,3654.61
LMK2_CLK_EN: R137.1 U8.4 | length 245.8
  L8 BOTTOM w7.75: U8.4@1908.9,3778.59 1997.03,3778.59 2056.85,3718.77 R137.1@2056.85,3645.7
LMK2_CLK_EN_N: R144.2 U8.6 | length 79.4
  L8 BOTTOM w5.25: R144.2@1838.39,3837.29 1839.86,3837.29 1854.34,3822.81 1873.69,3822.81 1880.66,3829.78 U8.6@1908.9,3829.78
LMK2_CLK_EN_P: R141.1 U8.5 | length 79.3
  L8 BOTTOM w5.25: R141.1@1838.39,3796.29 1841.06,3796.29 1855.58,3810.81 1873.87,3810.81 1880.49,3804.18 U8.5@1908.9,3804.18
LMK2_CLK_SEL: R139.2 U8.7 | length 80
  L8 BOTTOM w7.75: R139.2@1838.39,3878.29 1846.97,3878.29 1869.89,3855.37 U8.7@1908.9,3855.37
LMK2_OE: R138.1 U8.2 | length 120.1
  L8 BOTTOM w7.75: U8.2@1908.9,3727.41 1948.07,3727.41 1955.7,3719.79 R138.1@1955.7,3649.64
MCU_CLKOUT_RS_1: R5_1.2 U1_1.N9 | length 57.3
  L1 TOP w10.5: U1_1.N9@2299.94,3021.91 2305.71,3021.91 v2(2317.94,3034.14)
  L8 BOTTOM w7.75: R5_1.2@2283.71,3034.14 v2(2317.94,3034.14)
MCU_CLKOUT_RS_2: R5_2.2 U1_2.N9 | length 116.5
  L1 TOP w10.5: U1_2.N9@4617.94,2927.91 4623.71,2927.91 v2(4635.94,2940.14)
  L8 BOTTOM w7.75: R5_2.2@4543.9,2943.53 4547.29,2940.14 v2(4635.94,2940.14)
MCU_CLKOUT_RS_3: R5_3.2 U1_3.N9 | length 107.8
  L1 TOP w10.5: U1_3.N9@3614.94,3021.91 3620.71,3021.91 v2(3632.94,3034.14)
  L8 BOTTOM w7.75: R5_3.2@3551.46,3026.2 3559.4,3034.14 v2(3632.94,3034.14)
MCU_CLKOUT_RS_4: R5_4.2 U1_4.N9 | length 161.2
  L1 TOP w10.5: U1_4.N9@1129.94,2927.91 1135.71,2927.91 v2(1147.94,2940.14)
  L8 BOTTOM w7.75: R5_4.2@1014.55,2928.78 1049.3,2928.78 1060.66,2940.14 v2(1147.94,2940.14)
MSS_LOGGER_RS_1: R15_1.2 U1_1.R5 | length 174.6
  L1 TOP w6: R15_1.2@2108,3206 2112.72,3201.28 2155.62,3201.28 2232.64,3124.27 U1_1.R5@2248.76,3124.27
MSS_LOGGER_RS_2: R15_2.2 U1_2.R5 | length 169.7
  L1 TOP w4.9: R15_2.2@4430.9,3112 4471,3112 4552.73,3030.27 U1_2.R5@4566.76,3030.27
MSS_LOGGER_RS_3: R15_3.2 U1_3.R5 | length 175.9
  L1 TOP w4.9: R15_3.2@3422.9,3206 3422.9,3204 3434.73,3192.17 3487.54,3192.17 3555.44,3124.27 U1_3.R5@3563.76,3124.27
MSS_LOGGER_RS_4: R15_4.2 U1_4.R5 | length 176.8
  L1 TOP w4: 1057.68,3038.32 1063,3033 1076.03,3033 U1_4.R5@1078.76,3030.27
  L1 TOP w6: R15_4.2@937.9,3117 945.9,3109 987,3109 1057.68,3038.32
NERROR_OUT: DS2.2 J4.75 R150.1 R154.2 R156.2 R158.2 R160.2 | length 15844.1
  L1 TOP w10.5: v2(5894.06,3459.61) DS2.2@5894.06,3493.76
  L3 SIGNAL 1 w5.1: v2(3037.24,2539.49) 3037.24,2764 3237.87,2964.62 v2(3237.87,3047.64)
  L5 SIGNAL 2 w12: v2(842,3095.1) 853.64,3083.46 976.74,3083.46 1017.21,3123.92 1412.05,3123.92 1517.32,3018.65 1827.6,3018.65 1990.9,3181.95 2028.05,3181.95 v2(2037,3173)
  L6 SIGNAL 3 w6.9: v2(842,3095.1) 884.93,3138.03 884.93,3327.09 1126.05,3568.21 1126.05,4266.2 1392.79,4532.93 2018.75,4532.93 2143.65,4408.04 2507.62,4408.04 2581.18,4334.48 2823.74,4334.48 2851.61,4362.35 3142.35,4362.35 3188.33,4408.33 3188.33,4481.34 3208,4501.01 3208,4567.02 3285.48,4644.5 3482.19,4644.5 3528.8,4691.11 3732.33,4691.11 3766.82,4656.61 4004.49,4656.61 4132.37,4784.49 4625.46,4784.49 5363.21,4046.74 v2(5363.21,4005.06) 5335.8,4005.06 5296.17,4044.69 5129.07,4044.69 4454.58,3370.2 v2(4454.58,3252.7) ; v2(2037,3173) 2037,3212.19 2016.91,3232.28 1987.03,3232.28 1972.24,3247.07 1972.24,3268.92 2000.61,3297.29 2000.61,3343.48 2016.48,3359.35 2039.42,3359.35 2072.91,3325.87 2072.91,3276.54 2093.18,3256.27 2093.18,3208.04 2126.03,3175.19 2247.86,3175.19 2347.48,3274.82 2347.48,3392.58 2403.46,3448.57 2632.81,3448.57 2849.83,3231.54 2849.83,3124.4 2730.07,3004.64 2730.07,2915.71 2737.79,2907.99 2737.79,2879.36 3037.24,2579.9 v2(3037.24,2539.49) 3134.4,2442.34 3134.4,1016.48 3212.76,938.13 3212.76,746.72 3261.68,697.8 3261.68,657.35 3226.66,622.33 3005.67,622.33 v2(2986,642)
  L8 BOTTOM w7.75: v2(842,3095.1) 882.1,3095.1 R160.2@909,3122 ; v2(2037,3173) 2060.46,3173 2075.9,3157.56 R154.2@2075.9,3139.1 ; J4.75@2979.8,743.02 2979.8,694.2 2987,687 2987,643 v2(2986,642) R150.1@2986,610.42 ; v2@3240.29,3047.25 3259.58,3066.54 3289.73,3066.54 3325.19,3102 R158.2@3396.01,3102 ; v2(4454.58,3252.7) 4454.58,3220.59 4489.96,3185.21 4489.96,3167.72 4500.91,3156.76 4500.91,3086.36 4520.6,3066.67 R156.2@4520.6,3059.85 ; v2(5363.21,4005.06) 5471.63,4005.06 5582.13,3894.57 5582.13,3656.46 5619.82,3618.77 5734.9,3618.77 v2(5894.06,3459.61)
NERROR_OUT_LED: DS2.1 R193.1 | length 63.8
  L1 TOP w10.5: DS2.1@5951.15,3493.76 R193.1@5951.15,3557.54
NERROR_OUT_RS_1: R9_1.2 U1_1.N8 | length 320.9
  L1 TOP w10.5: U1_1.N8@2299.94,3047.5 2309.49,3057.05 2320.01,3057.05 2335.56,3072.6 v2(2354.99,3072.6)
  L8 BOTTOM w7.75: R9_1.2@2155.9,3176 2197,3176 2255.76,3117.24 2332.17,3117.24 2354.59,3094.82 2354.59,3072.2 v2(2354.99,3072.6)
NERROR_OUT_RS_2: R9_2.2 U1_2.N8 | length 169.7
  L1 TOP w10.5: U1_2.N8@4617.94,2953.5 4629.24,2964.8 4642.45,2964.8 4656.25,2978.6 v2(4672.99,2978.6)
  L8 BOTTOM w7.75: R9_2.2@4600.6,3020.95 4655.06,3020.95 4672.99,3003.02 v2(4672.99,2978.6)
NERROR_OUT_RS_3: R9_3.2 U1_3.N8 | length 155.4
  L1 TOP w10.5: U1_3.N8@3614.94,3047.5 3626.45,3059.01 3642.73,3059.01 3656.32,3072.6 v2(3669.99,3072.6)
  L8 BOTTOM w7.75: R9_3.2@3587.22,3084.16 3606.51,3084.16 3620.93,3069.73 3667.12,3069.73 v2(3669.99,3072.6)
NERROR_OUT_RS_4: R9_4.2 U1_4.N8 | length 319.9
  L1 TOP w10.5: U1_4.N8@1129.94,2953.5 1142.84,2966.4 1155.48,2966.4 1167.68,2978.6 v2(1184.99,2978.6)
  L8 BOTTOM w7.75: R9_4.2@985.9,3082 1026,3082 1084.74,3023.26 1160.76,3023.26 1184.71,2999.31 1184.71,2978.32 v2(1184.99,2978.6)
NetC9_1: C9.1 U5.3 | length 48.7
  L8 BOTTOM w10: C9.1@297.71,737.86 308.41,748.57 U5.3@342,748.57
NetC37_2: C37.2 R39.2 | length 27.6
  L8 BOTTOM w10: C37.2@753.8,1591.98 R39.2@781.41,1591.98
NetC38_2: C38.2 R40.2 | length 27.6
  L8 BOTTOM w10: R40.2@385.66,1591.98 C38.2@413.28,1591.98
NetC49_2: C49.2 R41.2 | length 27.6
  L8 BOTTOM w10: C49.2@753.8,1933.94 R41.2@781.41,1933.94
NetC50_2: C50.2 R42.2 | length 27.6
  L8 BOTTOM w10: R42.2@385.66,1933.94 C50.2@413.28,1933.94
NetC95_2: C95.2 R63.2 | length 27.6
  L8 BOTTOM w10: C95.2@5624.52,804.13 R63.2@5652.14,804.13
NetC96_2: C96.2 R64.2 | length 27.6
  L8 BOTTOM w10: R64.2@5256.39,804.13 C96.2@5284,804.13
NetC107_2: C107.2 R65.2 | length 27.6
  L8 BOTTOM w10: C107.2@5624.52,1146.09 R65.2@5652.14,1146.09
NetC108_2: C108.2 R66.2 | length 27.6
  L8 BOTTOM w10: R66.2@5256.39,1146.09 C108.2@5284,1146.09
NetDS3_2: DS3.2 Q1.3 | length 63
  L1 TOP w15: DS3.2@120.44,417.61 Q1.3@120.44,480.64
NetDS4_2: DS4.2 Q2.3 | length 64.3
  L1 TOP w10.5: Q2.3@4354.39,842.45 DS4.2@4354.39,906.78
NetDS5_2: DS5.2 Q3.3 | length 64.3
  L1 TOP w10.5: Q3.3@4660.83,842.45 DS5.2@4660.83,906.78
NetDS6_2: DS6.2 Q4.3 | length 64.3
  L1 TOP w10.5: Q4.3@4814.06,842.45 DS6.2@4814.06,906.78
NetDS7_2: DS7.2 Q5.3 | length 64.3
  L1 TOP w10.5: Q5.3@4507.61,842.45 DS7.2@4507.61,906.78
OSC_CLKOUT_RS_1: R2_1.2 U1_1.A14 | length 107.9
  L1 TOP w10.5: U1_1.A14@2607.03,2893.95 2625.79,2875.19 2625.79,2862.31 2653.2,2834.89 R2_1.2@2682.88,2834.89
OSC_CLKOUT_RS_2: R2_2.2 U1_2.A14 | length 119.1
  L1 TOP w8: U1_2.A14@4925.03,2799.95 4969.8,2755.18 4993.09,2755.18 4999.87,2748.4 R2_2.2@5022.77,2748.4
OSC_CLKOUT_RS_3: R2_3.2 U1_3.A14 | length 104
  L1 TOP w8: U1_3.A14@3922.03,2893.95 3935.88,2880.1 3953.48,2880.1 3991.17,2842.4 R2_3.2@4004.71,2842.4
OSC_CLKOUT_RS_4: R2_4.2 U1_4.A14 | length 173
  L1 TOP w10.5: U1_4.A14@1437.03,2799.95 1455.79,2781.19 1455.79,2760.07 1489.63,2726.23 R2_4.2@1567.14,2726.23
PMIC1_3V3: R34.1 R36.2 R49.2 R50.2 R51.2 R54.2 R56.2 R94.2 | length 368.7
  L8 BOTTOM w20: R36.2@92.28,1806.04 130.94,1806.04 v2(151.69,1826.79) R50.2@191.56,1826.79 ; R34.1@92.28,1875.1 97.28,1870.1 v2(151.69,1870.1) R51.2@191.56,1870.1 ; v2(147.58,1593.92) R54.2@187.46,1593.92 ; v2(147.58,1637.22) R56.2@187.46,1637.22 ; R49.2@988.28,1618.2 v2(1028.15,1618.2) ; R94.2@988.28,1868.27 v2(1028.15,1868.27)
PMIC1_12XX_1_1V0: C25.1 C27.1 C61.1 C62.1 L4.1 L5.1 L13.2 R43.1 | length 48.2
  L8 BOTTOM w15: C62.1@775.98,1445.28 R43.1@824.21,1445.28
PMIC1_12XX_4_1V0: C33.1 C35.1 C66.1 C67.1 L7.1 L8.1 L15.2 R48.1 | length 48.2
  L8 BOTTOM w15: C66.1@775.98,2080.64 R48.1@824.21,2080.64
PMIC1_12XX_14_1V2: C10.1 C64.1 C65.1 C161.1 L1.1 L3.1 L14.2 R45.1 | length 48.2
  L8 BOTTOM w15: R45.1@342.87,1445.28 C65.1@391.09,1445.28
PMIC1_12XX_14_1V8: C14.1 C68.1 C69.1 C86.1 L2.1 L6.1 L16.2 R35.1 R52.1 | length 48.2
  L8 BOTTOM w15: R52.1@342.87,2080.64 C68.1@391.09,2080.64
PMIC1_FB_B0: R43.2 U3.8 | length 422.1
  L8 BOTTOM w15: U3.8@658.34,1691.11 813.68,1691.11 833.58,1671.21 833.58,1606.08 864.21,1575.46 R43.2@864.21,1445.28
PMIC1_FB_B1: R45.2 U3.14 | length 411.9
  L8 BOTTOM w15: R45.2@302.87,1445.28 302.87,1623.1 370.88,1691.11 U3.14@508.73,1691.11
PMIC1_FB_B2: R48.2 U3.1 | length 413.6
  L8 BOTTOM w15: U3.1@658.34,1834.81 799.23,1834.81 864.21,1899.79 R48.2@864.21,2080.64
PMIC1_FB_B3: R52.2 U3.21 | length 413.6
  L8 BOTTOM w15: R52.2@302.87,2080.64 302.87,1899.79 367.85,1834.81 U3.21@508.73,1834.81
PMIC1_GPIO2: R54.1 TP7.1 U3.15 U5.5 | length 1886.2
  L3 SIGNAL 1 w5.1: v2(-60.26,1255.79) 39.14,1255.79 54.72,1271.37 287,1271.37 326.32,1310.69 326.32,1463.76 v2(234.7,1555.38)
  L8 BOTTOM w7.75: v2(-60.26,1255.79) -20.48,1216.01 -20.48,1073.71 160.17,893.06 354.43,893.06 439.5,807.99 439.5,782.27 447.61,774.16 U5.5@452.24,774.16 ; v2(234.7,1555.38) R54.1@234.7,1593.92 257.58,1593.92 271.32,1607.66 271.32,1644.49 TP7.1@293.43,1666.6 340.58,1713.75 U3.15@508.73,1713.75
PMIC1_GPIO3: R73.2 R94.1 U3.2 | length 469.5
  L8 BOTTOM w7.75: U3.2@658.34,1812.17 811.67,1812.17 867.77,1868.27 R94.1@941.03,1868.27 969.43,1896.67 1052.69,1896.67 R73.2@1081.09,1868.27
PMIC1_INTN: R50.1 U3.19 | length 284.1
  L8 BOTTOM w7.75: R50.1@238.81,1826.79 320.6,1826.79 354.9,1792.49 U3.19@508.73,1792.49
PMIC1_PGOOD: R73.1 R96.1 R204.2 | length 11347.4
  L1 TOP w6: v2(437.24,4296.19) 437.24,2642.76 212.32,2417.85 212.32,2031.35 262.88,1980.8 262.88,1959.84 242.13,1939.09 135.33,1939.09 110.09,1913.85 110.09,1740.66 131.84,1718.91 v2(131.84,1687.42) -0.76,1554.83 -0.76,1039.26 143.36,895.14 1054.68,895.14 1244.2,1084.67 1244.2,1192.77 1206.91,1230.06 1206.91,1845.31 v2(1183.95,1868.27) ; R204.2@3914.25,4020.74 3951.83,4020.74 3979.06,3993.5 v2(3979.06,3950.08)
  L8 BOTTOM w6: v2(131.84,1687.42) R96.1@171.71,1687.42 ; v2(437.24,4296.19) 1202.8,4296.19 1593.41,4686.79 2268.61,4686.79 2357.79,4597.62 2357.79,4451.15 2489.63,4319.31 2620.75,4319.31 2659.5,4358.06 2659.5,4408.86 2629.32,4439.03 2629.32,4482.91 2593.6,4518.63 2593.6,4619.76 2721.78,4747.95 2786.17,4747.95 2815.2,4718.91 2877.24,4718.91 2919.81,4676.34 3348.38,4676.34 3378.23,4706.19 3939.64,4706.19 4027.06,4618.77 4027.06,4504.11 3999.54,4476.6 3951.7,4476.6 3884.97,4409.87 3884.97,4338.86 3923.26,4300.57 4013.34,4300.57 4047.1,4266.81 4047.1,4018.12 v2(3979.06,3950.08) ; R73.1@1144.08,1868.27 v2(1183.95,1868.27)
PMIC1_PGOOD_RS: R56.1 R96.2 TP11.1 U3.16 | length 343.3
  L8 BOTTOM w6: R56.1@234.7,1637.22 R96.2@234.7,1687.42 245.57,1698.29 260.88,1698.29 TP11.1@293.43,1730.84 489.56,1730.84 492.15,1733.43 U3.16@508.73,1733.43
PMIC1_SCL: J4.72 R47.1 R98.1 R100.1 R102.1 R114.1 TP9.1 U3.5 | length 10164.4
  L1 TOP w10.5: v2(788.92,3288.1) 788.92,3256.99 646.81,3114.88 646.81,2750.57 885.85,2511.53 885.85,1773.33 v2(941.03,1718.15)
  L5 SIGNAL 2 w12: v2(788.92,3288.1) 822.67,3321.85 1169.51,3321.85 1341.82,3149.55 1419.85,3149.55 1518.86,3050.54 1755.49,3050.54 1828.46,3123.5 1870.63,3123.5 1923.8,3176.67 1923.8,3232.94 v2(1951.03,3260.18) ; v2(3448.24,3447.14) 3504.12,3391.26 3709.95,3391.26 3842.13,3523.44 4080.51,3523.44 4121.81,3482.15 4121.81,3401.27 4009.99,3289.45 4009.99,3196.17 4064.8,3141.35 4251.08,3141.35 4274.15,3164.42 4295.91,3164.42 4325.82,3194.34 v2(4328.61,3194.34)
  L6 SIGNAL 3 w6.9: v2(1668.76,1718.15) 1668.76,1429.75 2476.77,621.73 2862.04,621.73 v2(2912,671.69) ; v2(1951.03,3260.18) 1958.17,3267.31 1958.17,3275.07 1982.95,3299.86 1982.95,3349.94 2008.64,3375.63 2053.37,3375.63 2093.71,3335.29 2093.71,3279.31 2111.37,3261.65 2111.37,3215.09 2134.29,3192.17 2229.13,3192.17 2330.46,3293.5 2330.46,3411.09 2386.94,3467.57 2692.31,3467.57 2798.84,3361.04 v2(2828.84,3361.04)
  L8 BOTTOM w7.75: U3.5@658.34,1753.12 676.46,1753.12 681.35,1748.23 TP9.1@885.78,1748.23 R47.1@941.03,1748.23 v2(941.03,1718.15) v2(1668.76,1718.15) ; v2(788.92,3288.1) 811.55,3265.46 917.54,3265.46 933.88,3249.12 R114.1@933.88,3235.9 ; v2(1951.03,3260.18) 1981.56,3290.71 2001.59,3290.71 2017.24,3275.06 R98.1@2064.31,3275.06 ; v2(2828.84,3361.04) 3015.95,3548.15 3399.39,3548.15 3448.24,3499.3 v2(3448.24,3447.14) R102.1@3448.24,3373.71 ; v2(2912,671.69) 2920.75,680.44 J4.72@2920.75,743.02 ; v2(4328.61,3194.34) 4343.72,3179.22 R100.1@4386.98,3179.22
PMIC1_SDA: J4.73 R46.2 R99.1 R101.1 R112.1 R125.1 TP10.1 U3.6 | length 9791.9
  L1 TOP w8: R112.1@3508.27,3457.99 v2(3508.27,3500.51) ; v2(4259.95,3214.65) 4276.6,3198 R101.1@4291.06,3198
  L1 TOP w10.5: v2(761.74,3265.93) 627.45,3131.64 627.45,2730.66 865.28,2492.83 865.28,1728.88 v2(941.03,1653.13)
  L5 SIGNAL 2 w12: v2(761.74,3265.93) 761.74,3307.2 811.01,3356.47 1181.41,3356.47 1363.78,3174.1 1428.23,3174.1 1521.42,3080.91 1737.13,3080.91 1819.45,3163.23 1855.35,3163.23 1893.28,3201.16 1893.28,3274.97 1923.58,3305.27 v2(1954.65,3305.27) ; v2(3508.27,3500.51) 3508.27,3456.2 3543.25,3421.22 3624.76,3421.22 3779.22,3575.68 4107.74,3575.68 4168.22,3515.2 4168.22,3364.26 4090.15,3286.18 4090.15,3210.22 4119.57,3180.8 4192.99,3180.8 4226.84,3214.65 v2(4259.95,3214.65)
  L6 SIGNAL 3 w6.9: v2(1642.42,1676.33) 1642.42,1426.03 2460.39,608.07 2897.07,608.07 v2(2939,650) ; v2(1954.65,3305.27) 1954.65,3343.47 2003.18,3392 2085.49,3392 2111.63,3365.85 2111.63,3316.78 2129.68,3298.73 2155.47,3298.73 2169.82,3284.38 2270.05,3284.38 2312.56,3326.89 2312.56,3436.17 2358.84,3482.45 2738.43,3482.45 v2(2824.62,3396.26)
  L8 BOTTOM w7.75: U3.6@658.34,1733.43 835.56,1733.43 TP10.1@885.78,1683.21 R46.2@941.03,1683.21 v2(941.03,1653.13) 1070.39,1653.13 1093.59,1676.33 v2(1642.42,1676.33) ; R125.1@761.74,3236.1 v2(761.74,3265.93) ; v2(1954.65,3305.27) R99.1@1954.65,3335.1 ; v2(2824.62,3396.26) 2996.4,3568.04 3440.73,3568.04 v2(3508.27,3500.51) ; v2(2939,650) 2940.43,651.43 J4.73@2940.43,743.02
PMIC1_SW_B0: C37.1 L13.1 U3.10 | length 130.8
  L8 BOTTOM w9: U3.10@603.22,1702.33 603.22,1641.47 652.66,1592.04
PMIC1_SW_B1: C38.1 L14.1 U3.12 | length 130.8
  L8 BOTTOM w9: 514.42,1592.04 563.85,1641.47 U3.12@563.85,1702.33
PMIC1_SW_B2: C49.1 L15.1 U3.25 | length 130.8
  L8 BOTTOM w9: U3.25@603.22,1823.59 603.22,1884.45 652.66,1933.89
PMIC1_SW_B3: C50.1 L16.1 U3.23 | length 130.8
  L8 BOTTOM w9: 514.42,1933.89 563.85,1884.45 U3.23@563.85,1823.59
PMIC1_VANA: C63.1 R44.2 TP14.1 U3.18 | length 343.1
  L8 BOTTOM w9: 490.46,1772.8 U3.18@508.73,1772.8
  L8 BOTTOM w12: C63.1@219.53,1739.74 234.75,1739.74 245.28,1750.27 R44.2@245.28,1783.21 245.28,1787.47 252.89,1795.08 TP14.1@293.43,1795.08 324.97,1795.08 343.67,1776.38 486.89,1776.38 490.46,1772.8
PMIC1_VIN_B0: C40.1 C41.1 C42.1 C43.1 L9.2 U3.9
  other v3: 708.82,1626.03 708.82,1645.04 727.45,1645.04 708.82,1664.05 727.45,1664.05 746.08,1664.05
PMIC1_VIN_B1: C45.1 C46.1 C47.1 C48.1 L10.2 U3.13
  other v3: 458.26,1626.03 439.63,1645.04 458.26,1645.04 421,1664.05 439.63,1664.05 458.26,1664.05
PMIC1_VIN_B2: C52.1 C53.1 C54.1 C55.1 L11.2 U3.26
  other v3: 708.82,1861.87 727.45,1861.87 746.08,1861.87 708.82,1880.88 727.45,1880.88 708.82,1899.89
PMIC1_VIN_B3: C57.1 C58.1 C59.1 C60.1 L12.2 U3.22
  other v3: 421,1861.87 439.63,1861.87 458.26,1861.87 439.63,1880.88 458.26,1880.88 458.26,1899.89
PMIC2_3V3: R59.1 R60.2 R74.2 R78.2 R80.2 R95.2 | length 215.1
  L8 BOTTOM w20: R60.2@4912.9,1044.19 v2(4912.9,1084.06) ; R59.1@4978.78,1044.19 v2(4978.78,1084.06) ; v2(5018.31,919.56) R80.2@5058.18,919.56 ; v2(5022.42,1043.93) R74.2@5062.29,1043.93 ; v2(5038.8,811.98) R78.2@5065.83,811.98 ; R95.2@5859,1090.42 v2(5859,1118.98)
PMIC2_12XX_2_1V0: C82.1 C84.1 C119.1 C120.1 L20.1 L21.1 L29.2 R67.1 | length 48.2
  L8 BOTTOM w15: C120.1@5646.71,657.42 R67.1@5694.93,657.42
PMIC2_12XX_3_1V0: C90.1 C92.1 C124.1 C125.1 L23.1 L24.1 L31.2 R72.1 | length 48.2
  L8 BOTTOM w15: C124.1@5646.71,1292.79 R72.1@5694.93,1292.79
PMIC2_12XX_23_1V2: C70.1 C122.1 C123.1 C153.1 L17.1 L19.1 L30.2 R69.1 | length 48.2
  L8 BOTTOM w15: R69.1@5213.59,657.42 C123.1@5261.82,657.42
PMIC2_12XX_23_1V8: C74.1 C126.1 C127.1 C157.1 L18.1 L22.1 L32.2 R76.1 | length 48.2
  L8 BOTTOM w15: R76.1@5213.59,1292.79 C126.1@5261.82,1292.79
PMIC2_FB_B0: R67.2 U4.8 | length 414.1
  L8 BOTTOM w15: U4.8@5529.07,903.26 5670.7,903.26 5712.74,861.22 5712.74,809.8 5734.93,787.61 R67.2@5734.93,657.42
PMIC2_FB_B1: R69.2 U4.14 | length 406.2
  L8 BOTTOM w15: R69.2@5173.59,657.42 5173.59,825.65 5251.2,903.26 U4.14@5379.46,903.26
PMIC2_FB_B2: R72.2 U4.1 | length 413.6
  L8 BOTTOM w15: U4.1@5529.07,1046.96 5669.95,1046.96 5734.93,1111.94 R72.2@5734.93,1292.79
PMIC2_FB_B3: R76.2 U4.21 | length 413.6
  L8 BOTTOM w15: R76.2@5173.59,1292.79 5173.59,1111.94 5238.57,1046.96 U4.21@5379.46,1046.96
PMIC2_GPIO2: R78.1 TP24.1 U4.15 | length 330.3
  L8 BOTTOM w7.75: 5114.42,811.98 5128.3,811.98 5164.16,847.84 TP24.1@5164.16,878.74 5211.31,925.89 U4.15@5379.46,925.89
PMIC2_GPIO3: R75.2 R95.1 U4.2 | length 498.4
  L8 BOTTOM w7.75: U4.2@5529.07,1024.32 5688.32,1024.32 5754.41,1090.42 R95.1@5811.76,1090.42 5811.76,1126.39 5830.7,1145.33 5891.99,1145.33 5914.54,1122.77 R75.2@5914.54,1090.42
PMIC2_INTN: R74.1 U4.19 | length 286.2
  L8 BOTTOM w7.75: R74.1@5109.53,1043.93 5114.53,1038.93 5190.44,1038.93 5224.74,1004.63 U4.19@5379.46,1004.63
PMIC2_PGOOD: R75.1 R97.1 R205.2 | length 7731.5
  L1 TOP w6: R205.2@3914.25,3971.03 3914.25,3945.93 3942.13,3918.05 v2(3978.93,3918.05) ; v2(5002.56,869.37) 5076.39,869.37 5176.37,769.38 5176.37,262.34 5249.54,189.17 5353.33,189.17 5371.87,170.63 5805.61,170.63 5836.8,201.81 6064.23,201.81 6136.34,273.92 6136.34,1038.94 v2(6084.86,1090.42)
  L3 SIGNAL 1 w6: v2(5623.99,3918.05) 5659.18,3882.85 5659.18,2434.63 6084.86,2008.95 v2(6084.86,1090.42)
  L8 BOTTOM w6: v2(3978.93,3918.05) 4165.64,4104.76 5061.78,4104.76 5212.11,3954.44 5272.72,3954.44 5349.85,4031.56 5510.47,4031.56 v2(5623.99,3918.05) ; v2(5002.56,869.37) R97.1@5042.43,869.37 ; R75.1@5977.53,1090.42 v2(6084.86,1090.42)
PMIC2_PGOOD_RS: R80.1 R97.2 TP28.1 U4.16 | length 335
  L8 BOTTOM w6: R97.2@5105.43,869.37 R80.1@5105.43,919.56 5140.74,919.56 TP28.1@5164.16,942.99 5360.28,942.99 5362.88,945.58 U4.16@5379.46,945.58
PMIC2_SW_B0: C95.1 L29.1 U4.10 | length 130.8
  L8 BOTTOM w9: U4.10@5473.95,914.48 5473.95,853.61 5523.38,804.18
PMIC2_SW_B1: C96.1 L30.1 U4.12 | length 130.8
  L8 BOTTOM w9: 5385.14,804.18 5434.58,853.61 U4.12@5434.58,914.48
PMIC2_SW_B2: C107.1 L31.1 U4.25 | length 130.8
  L8 BOTTOM w9: U4.25@5473.95,1035.74 5473.95,1096.6 5523.38,1146.03
PMIC2_SW_B3: C108.1 L32.1 U4.23 | length 130.8
  L8 BOTTOM w9: 5385.14,1146.03 5434.58,1096.6 U4.23@5434.58,1035.74
PMIC2_TMPSNS_SCL: J5.49 R71.1 R170.2 TP26.1 U4.5 | length 6278.8
  L1 TOP w10.5: v2(3624,4485.92) R170.2@3624,4523
  L3 SIGNAL 1 w5.1: v2(3624,4485.92) 3653.42,4485.92 3768.36,4370.98 3896.27,4370.98 3924.99,4342.26 5463.78,4342.26 5683.65,4122.4 5683.65,2452.15 6111.24,2024.55 v2(6111.24,990.66)
  L8 BOTTOM w7.75: v2(3624,4485.92) 3624,4442.55 3647,4419.54 3647,4395.99 J5.49@3649.09,4393.9 ; U4.5@5529.07,965.26 5547.19,965.26 5552.07,960.38 TP26.1@5756.51,960.38 R71.1@5811.76,960.38 5840.11,932.02 5998.32,932.02 6056.96,990.66 v2(6111.24,990.66)
PMIC2_TMPSNS_SDA: J5.48 R70.2 R169.2 TP27.1 U4.6 | length 6404.8
  L3 SIGNAL 1 w5.1: v2(3612,4306.48) 3650.96,4345.44 3894.78,4345.44 3997.93,4242.3 4138,4242.3 4208.43,4312.73 5464.31,4312.73 5579.62,4197.42 5579.62,2467.12 6059.57,1987.17 6059.57,1082.13 6085.07,1056.64 6085.07,952.26 v2(6059.57,926.77)
  L8 BOTTOM w7.75: R169.2@3583,4500 3603.6,4479.4 3603.6,4441.4 3629.41,4415.59 3629.41,4328.89 3612,4311.48 v2(3612,4306.48) ; U4.6@5529.07,945.58 5696.29,945.58 5746.51,895.36 TP27.1@5756.51,895.36 R70.2@5811.76,895.36 5843.77,863.35 5996.15,863.35 v2(6059.57,926.77)
PMIC2_VANA: C121.1 R68.2 TP31.1 U4.18 | length 333.6
  L8 BOTTOM w9: 5361.19,984.95 U4.18@5379.46,984.95
  L8 BOTTOM w12: C121.1@5090.26,956.89 5105.48,956.89 5116.01,967.42 R68.2@5116.01,995.35 ; R68.2@5116.01,1000.35 5122.88,1007.23 TP31.1@5164.16,1007.23 5195.7,1007.23 5214.4,988.53 5357.61,988.53 5361.19,984.95
PMIC2_VIN_B0: C98.1 C99.1 C100.1 C101.1 L25.2 U4.9
  other v3: 5579.55,838.18 5579.55,857.18 5598.17,857.18 5579.55,876.19 5598.17,876.19 5616.8,876.19
PMIC2_VIN_B1: C103.1 C104.1 C105.1 C106.1 L26.2 U4.13
  other v3: 5328.98,838.18 5310.35,857.18 5328.98,857.18 5291.72,876.19 5310.35,876.19 5328.98,876.19
PMIC2_VIN_B2: C110.1 C111.1 C112.1 C113.1 L27.2 U4.26
  other v3: 5579.55,1074.02 5598.17,1074.02 5616.8,1074.02 5579.55,1093.03 5598.17,1093.03 5579.55,1112.04
PMIC2_VIN_B3: C115.1 C116.1 C117.1 C118.1 L28.2 U4.22
  other v3: 5291.72,1074.02 5310.35,1074.02 5328.98,1074.02 5310.35,1093.03 5328.98,1093.03 5328.98,1112.04
PMIC_BUCK_EN: R49.1 R55.2 R145.1 TP6.1 TP23.1 U3.7 U4.7 | length 15235.2
  L8 BOTTOM w7.75: U3.7@658.34,1713.75 825.12,1713.75 854.14,1684.73 854.14,1662.04 865.42,1650.77 865.42,1638.56 TP6.1@885.78,1618.2 R49.1@941.03,1618.2 975.51,1583.71 1046.61,1583.71 R55.2@1081.09,1618.2 ; R145.1@3501,4537.9 3501,4589.03 3513.1,4601.13 3513.1,4643.39 3490.76,4665.73 3390.77,4665.73 3358.49,4633.46 2917.07,4633.46 2867.35,4683.17 2801.25,4683.17 2719.47,4601.39 2652.71,4601.39 2622.7,4571.38 2622.7,4526.02 2654.82,4493.9 2654.82,4449.72 2687.05,4417.49 2687.05,4327.24 2664.77,4304.96 2664.77,4295.1 2511.4,4141.73 2382.65,4141.73 2292.3,4232.07 2292.3,4558.58 2248.6,4602.27 2101.46,4602.27 2047.46,4548.27 1697.99,4548.27 1312.5,4162.78 1312.5,3483.7 1474.36,3321.83 1807.31,3321.83 1875.57,3253.56 1875.57,3076.06 1834.81,3035.3 1834.81,2953.78 1875.57,2913.02 1875.57,2559.18 1651.04,2334.65 1651.04,1829.33 1711.99,1768.38 1711.99,1654.44 1681.67,1624.12 1251.68,1624.12 1230.96,1644.84 1107.73,1644.84 R55.2@1081.09,1618.2 ; U4.7@5529.07,925.89 5678.1,925.89 5746.71,857.28 5746.71,840.14 TP23.1@5756.51,830.34 ; TP23.1@5746.51,830.34 TP23.1@5756.51,830.34 ; R55.2@1081.09,1618.2 1091.22,1608.06 1091.22,1578.84 1131.75,1538.31 1378.16,1538.31 1640.5,1275.97 1640.5,110.27 1808.8,-58.02 5491.3,-58.02 5693.13,143.8 5960.78,143.8 6034.87,217.89 6034.87,744.07 5948.6,830.34 TP23.1@5756.51,830.34
PMIC_BUCKEN_CONN: J5.46 R145.2 | length 171.9
  L8 BOTTOM w7.75: R145.2@3501,4500.1 3590.04,4411.06 J5.46@3590.04,4365.06
PMIC_CLKOUT_RS_1: R4_1.2 U1_1.P13 | length 112.3
  L1 TOP w4: 2198,2904 2223,2904 2225.55,2906.55 2254.69,2906.55 2267.69,2919.55 U1_1.P13@2274.35,2919.55
  L1 TOP w10.5: R4_1.2@2171,2910 2177,2904 2198,2904
PMIC_CLKOUT_RS_2: R4_2.2 U1_2.P13 | length 110.2
  L1 TOP w4: 4516,2812.55 4572.69,2812.55 4573.14,2813 4585.71,2825.55 U1_2.P13@4592.35,2825.55
  L1 TOP w10.5: R4_2.2@4489,2816 4492.45,2812.55 4516,2812.55
PMIC_CLKOUT_RS_3: R4_3.2 U1_3.P13 | length 110.2
  L1 TOP w4: 3513,2906.55 3569.69,2906.55 3582.71,2919.55 U1_3.P13@3589.35,2919.55
  L1 TOP w10.5: R4_3.2@3486,2910 3489.45,2906.55 3513,2906.55
PMIC_CLKOUT_RS_4: R4_4.2 U1_4.P13 | length 110.2
  L1 TOP w4: 1028,2812.55 1084.69,2812.55 1085.14,2813 1097.71,2825.55 U1_4.P13@1104.35,2825.55
  L1 TOP w10.5: R4_4.2@1001,2816 1004.45,2812.55 1028,2812.55
PMIC_NRST: R51.1 R58.2 R146.1 TP4.1 TP21.1 U3.20 U4.20 | length 15040.2
  L1 TOP w10.5: v2(362.67,4267.32) 410.71,4219.28 410.71,2670.5 188.85,2448.64 188.85,2019.18 v2(238.81,1969.22) 226.91,1957.32 127.48,1957.32 -26.25,1803.59 -26.25,1016.76 121.63,868.88 2265.67,868.88 2734.72,399.83 3936.26,399.83 4290.4,45.69 4803.14,45.69 5046.46,289.01 5046.46,758.39 4968.34,836.51 4968.34,887.55 4947.72,908.17 4947.72,957.35 4977.57,987.2 4977.57,1039.15 5042.79,1104.37 v2(5131.26,1104.37)
  L8 BOTTOM w7.75: v2(238.81,1969.22) R58.2@238.81,1913.4 R51.1@238.81,1870.1 247.8,1870.1 258.57,1859.32 TP4.1@293.43,1859.32 310.94,1841.81 328.23,1841.81 357.87,1812.17 U3.20@508.73,1812.17 ; v2(362.67,4267.32) 390.24,4239.75 1254.83,4239.75 1656.36,4641.29 2259.02,4641.29 2321.82,4578.48 2321.82,4301.59 2374.14,4249.28 2579.19,4249.28 2673.04,4343.13 2673.04,4412.48 2642.07,4443.45 2642.07,4487.5 2607.77,4521.81 2607.77,4586.82 2648.38,4627.43 2715.19,4627.43 2787.25,4699.49 2874.82,4699.49 2920.33,4653.97 3352.77,4653.97 3383.35,4684.55 3512.84,4684.55 3534.77,4662.62 3534.77,4588.92 3542,4581.69 R146.1@3542,4547.34 ; v2(5131.26,1104.37) TP21.1@5164.16,1071.47 5185.74,1071.47 5232.89,1024.32 U4.20@5379.46,1024.32
PMIC_NRST_CONN: J5.47 R146.2 | length 163.1
  L8 BOTTOM w7.75: R146.2@3542,4500.1 3542,4477.13 3609.72,4409.41 J5.47@3609.72,4365.06
QSPI_CLK_1: R7_1.2 U2_1.6 | length 785.2
  L1 TOP w10.5: R7_1.2@2012.41,2921.02 2012.41,2803.61 v2@2051.6,2764.42
  L8 BOTTOM w7.75: v2@2051.6,2764.42 2073.45,2764.42 2118.41,2719.46 2118.41,2665.2 2130.85,2652.76 2130.85,2403.81 2165.66,2369 2165.66,2272.28 2136.83,2243.45 U2_1.6@2117.46,2243.45
  other v2: 2051.6,2764.3
QSPI_CLK_2: R7_2.2 U2_2.6 | length 640.8
  L1 TOP w6: R7_2.2@4347.63,2778.94 4347.63,2742.84 4367,2723.47 4367,2705.02
  L1 TOP w10.5: 4367,2705.02 4367,2695.47 4342.56,2671.04 4342.56,2422.53 v2(4370.1,2395)
  L8 BOTTOM w7.75: U2_2.6@4340.2,2208.17 4365.55,2208.17 4386.06,2228.68 4386.06,2379.04 v2(4370.1,2395)
QSPI_CLK_3: R7_3.2 U2_3.6 | length 477.3
  L1 TOP w10.5: v3(3205.49,2969) R7_3.2@3245.02,2969
  L8 BOTTOM w7.75: U2_3.6@3117.72,3224 3075.65,3224 3061.82,3210.17 3041.62,3210.17 3014.98,3183.53 3014.98,3117.13 3163.11,2969 v3(3205.49,2969)
QSPI_CLK_4: R7_4.2 U2_4.6 | length 1075.2
  L1 TOP w10.5: v2(777.48,2851.34) R7_4.2@810.24,2851.34
  L6 SIGNAL 3 w6.9: v2(777.48,2851.34) 751.77,2851.34 714.09,2889.03 714.09,2976.16 658.89,3031.36 658.89,3328.48 914.78,3584.37 v2(914.78,3676.7)
  L8 BOTTOM w7.75: U2_4.6@900.89,3717.86 900.89,3690.59 v2(914.78,3676.7)
QSPI_CLK_RS_1: R7_1.1 U1_1.R10 | length 292.5
  L1 TOP w4: 2042.87,2977.46 2049.7,2984.29 2049.7,3004.7 2070,3025 2154.3,3025 2167.55,3011.75 2216.25,3011.75 2231.68,2996.32 U1_1.R10@2248.76,2996.31
  L1 TOP w10.5: R7_1.1@2012.41,2947 2042.87,2977.46
QSPI_CLK_RS_2: R7_2.1 U1_2.R10 | length 332
  L1 TOP w4: 4383.9,2924.41 4390.5,2931 4474,2931 4491,2914 4537,2914 4548.68,2902.32 U1_2.R10@4566.76,2902.32
  L1 TOP w6: R7_2.1@4347.63,2804.93 4347.63,2817.53 4373.07,2842.96 4373.07,2913.57 4383.9,2924.41
QSPI_CLK_RS_3: R7_3.1 U1_3.R10 | length 369.9
  L1 TOP w4: 3347.48,2951.49 3370,2974 3370,3010 3385,3025 3471,3025 3485,3011 3532,3011 3546.68,2996.32 U1_3.R10@3563.76,2996.31
  L1 TOP w10.5: R7_3.1@3271,2969 3296.33,2943.67 3339.67,2943.67 3347.48,2951.49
